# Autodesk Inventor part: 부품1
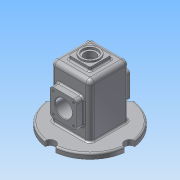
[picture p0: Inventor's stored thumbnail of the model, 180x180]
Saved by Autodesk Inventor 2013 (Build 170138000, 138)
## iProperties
Created: 2018-07
Part Number: 부품1
Material: 알루미늄 6061
Document SubType Name: Modeling
Designer: Administrator
Mass: 1013.28 g
Surface Area: 1076.76 cm^2
Volume: 373.903 cm^3
Density: 2.71 g/cm^3
Author: Administrator
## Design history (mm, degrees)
sketch "스케치1"
  geometry: L1 (-37, -37)-(37, -37); L2 (37, -37)-(37, 37); L3 (37, 37)-(-37, 37); L4 (-37, 37)-(-37, -37); L5 (-37, -37)-(37, 37); L6 (37, -37)-(-37, 37); 1 further point
  constraints: 12 end point, 2 midpoint, 2 parallel, 1 horizontal, 1 perpendicular
  dimensions: "d0" = 74 distance of L2.end L3.end; "d2" = 74 distance of L3.end L1.start
extrude "돌출1" new body sketch "스케치1" distance "d3" = 110; taper "d4" = 0 deg
sketch "스케치2"
  geometry: L1 (-32, -32)-(32, -32); L2 (32, -32)-(32, 32); L3 (32, 32)-(-32, 32); L4 (-32, 32)-(-32, -32); L5 (-32, -32)-(32, 32); L6 (32, -32)-(-32, 32); 1 further point
  constraints: 12 end point, 2 midpoint, 2 parallel, 1 horizontal, 1 perpendicular
  dimensions: "d5" = 64 distance of L2.end L3.end; "d7" = 64 distance between parallel lines of L1 L3
extrude "돌출2" cut sketch "스케치2" distance "d8" = 105; taper "d9" = 0 deg
node "작업 평면1"
sketch "스케치3"
  geometry: L1 (-25, 80)-(25, 80); L2 (25, 80)-(25, 30); L3 (25, 30)-(-25, 30); L4 (-25, 30)-(-25, 80); L5 (-37, 0)-(37, 0) reference; 4 further points
  constraints: 8 end point, 3 midpoint, 2 parallel, 2 vertical alignment, 1 horizontal, 1 perpendicular
  dimensions: "d11" = 50 distance of L1.start L1.end; "d13" = 50 distance of L3.end L1.start; "d14" = 30 distance between parallel lines of L5 L3
extrude "돌출3" join sketch "스케치3" stored distance "d15" = 105; taper "d16" = 0 deg
fillet "모깎기1" dims "d22" = 6
sketch "스케치5"
  geometry: A1 r 6 centre (-19, 36) between (-25, 36) and (-19, 30) reference; A2 r 6 centre (19, 36) between (19, 30) and (25, 36) reference; A3 r 6 centre (19, 74) between (25, 74) and (19, 80) reference; A4 r 6 centre (-19, 74) between (-19, 80) and (-25, 74) reference; 5 further points
  constraints: 4 coincident
hole "구멍1" sketch "스케치5" at (-19, 74), (-19, 36), (19, 36), (19, 74) diameter "d23" = 3.459; stored, may be unused: countersink angle "d27" = 90 deg, drill point angle "d29" = 118 deg; dims "d24" = 8, "d25" = 4, "d26" = 2, "d28" = 10
fillet "모깎기2" dims "d33" = 8
fillet "모깎기3" dims "d34" = 3
fillet "모깎기4" dims "d35" = 3
sketch "스케치6"
  geometry: L1 (32.548, 25)-(30, 32); L2 (102, 32)-(0, 32) reference; L3 (0, 32)-(0, 29) reference; L4 (32.548, 25)-(55, 25); L5 (72, 50)-(38, 50) reference; L6 (55, 50)-(55, 25); L7 (55, 50)-(30, 50); L8 (30, 50)-(30, 32); 1 further point
  constraints: 10 end point, 3 perpendicular, 2 point on line, 1 midpoint
  dimensions: "d36" = 110 deg angle of L1 L2; "d37" = 30 distance from line of L3 L1.end; "d38" = 7 distance between parallel lines of L2 L4
revolve "회전1" sketch "스케치6" stored, may be unused: angle "d39" = 90 deg
fillet "모깎기5" dims "d40" = 6
fillet "모깎기6" dims "d41" = 3
sketch "스케치7"
  geometry: A1 r 6 centre (38, -6) between (44, -6) and (38, 0) reference; A2 r 6 centre (0, -6) between (0, 0) and (-6, -6) reference; A3 r 6 centre (0, -44) between (-6, -44) and (0, -50) reference; A4 r 6 centre (38, -44) between (38, -50) and (44, -44) reference; 5 further points
  constraints: 4 coincident
hole "구멍2" sketch "스케치7" at (0, -6), (0, -44), (38, -44), (38, -6) diameter "d42" = 3.459; stored, may be unused: countersink angle "d46" = 90 deg, drill point angle "d48" = 118 deg; dims "d43" = 8, "d44" = 4, "d45" = 2, "d47" = 10
sketch "스케치8"
  geometry: L1 (-29, 0)-(29, 0) reference; L2 (-29, 110)-(29, 110) reference; C1 r 16 at (0, 55); 2 further points
  constraints: 1 centre point, 1 midpoint, 1 vertical alignment
  dimensions: "d49" = 55 distance from line of L1 C1.centre; "d50" = 32 diameter of C1
extrude "돌출5" cut sketch "스케치8" stored distance "d51" = 105; taper "d52" = 0 deg
chamfer "모따기2" distance "d53" = 1; stored, may be unused: second distance "d54" = 2, angle "d55" = 45 deg
chamfer "모따기3" distance "d56" = 1; stored, may be unused: second distance "d57" = 2, angle "d58" = 45 deg
fillet "모깎기7" dims "d59" = 8
sketch "스케치9"
  geometry: C1 r 75 at (0, 0); 1 further point
  constraints: 1 centre point, 1 coincident
  dimensions: "d60" = 150 diameter of C1
extrude "돌출6" join sketch "스케치9" distance "d62" = 10; taper "d63" = 0 deg
fillet "모깎기8" dims "d64" = 3
fillet "모깎기9" dims "d65" = 3
sketch "스케치10"
  geometry: C1 r 72 at (0, 0) reference; C2 r 10 at (0, 75); 1 further point
  constraints: 2 vertical alignment, 1 centre point, 1 other
  dimensions: "d66" = 20 diameter of C2
extrude "돌출7" cut sketch "스케치10" distance "d68" = 10; taper "d69" = 0 deg
fillet "모깎기10" dims "d73" = 3
sketch "스케치11"
  geometry: L1 (0, 0)-(58, 0) reference; L2 (38.978, -102)-(103.333, -102) reference; 3 further points
  constraints: 1 midpoint, 1 vertical alignment, 1 other
  dimensions: "d91" = 90 distance from line of L2 point (29, -12)
sketch "스케치12"
  geometry: L1 (-20, -20)-(20, -20); L2 (20, -20)-(20, 20); L3 (20, 20)-(-20, 20); L4 (-20, 20)-(-20, -20); L5 (-20, -20)-(20, 20); L6 (20, -20)-(-20, 20); 1 further point
  constraints: 12 end point, 2 midpoint, 2 parallel, 1 horizontal, 1 perpendicular
  dimensions: "d74" = 40 distance of L1.end L2.end; "d76" = 40 distance of L1.start L1.end
extrude "돌출8" join sketch "스케치12" distance "d77" = 7; taper "d78" = 0 deg
sketch "스케치13"
  geometry: C1 r 17.5 at (0, 0); 1 further point
  constraints: 1 centre point, 1 coincident
  dimensions: "d79" = 35 diameter of C1
extrude "돌출9" join sketch "스케치13" distance "d81" = 3; taper "d82" = 0 deg
sketch "스케치14"
  geometry: C1 r 17.5 at (0, 0) reference; C2 r 14 at (0, 0)
  constraints: 1 centre point, 1 coincident
  dimensions: "d83" = 28 diameter of C2
extrude "돌출10" cut sketch "스케치14" distance "d85" = 4; taper "d86" = 0 deg
sketch "스케치15"
  geometry: C1 r 14 at (0, 0) reference; C2 r 10.5 at (0, 0)
  constraints: 1 centre point, 1 coincident
  dimensions: "d87" = 21 diameter of C2
extrude "돌출11" cut sketch "스케치15" stored distance "d89" = 4; taper "d90" = 0 deg
feature "엠보싱1" dims "d11" = 50, "d13" = 50, "d14" = 30, "d92" = 0.5, "d93" = 0
sketch "스케치16"
  geometry: L1 (-32, -32)-(32, -32); L2 (32, -32)-(32, 32); L3 (32, 32)-(-32, 32); L4 (-32, 32)-(-32, -32); L5 (-32, -32)-(32, 32); L6 (32, -32)-(-32, 32); C1 r 10.5 at (0, 0) reference; A1 r 75 centre (0, 0) between (9.978, -74.333) and (74.333, -9.978) reference
  constraints: 12 end point, 2 midpoint, 2 parallel, 1 horizontal, 1 perpendicular
  dimensions: "d94" = 64 distance of L2.end L3.end; "d96" = 64 distance of L3.end L1.start
extrude "돌출12" cut sketch "스케치16" distance "d97" = 10; taper "d98" = 0 deg
fillet "모깎기11" dims "d99" = 3
fillet "모깎기12" dims "d100" = 3
fillet "모깎기13" dims "d101" = 3
node "솔리드1"
mirror "대칭1"
pattern_circular "원형 패턴1" dims angle "d71" = 360 deg
